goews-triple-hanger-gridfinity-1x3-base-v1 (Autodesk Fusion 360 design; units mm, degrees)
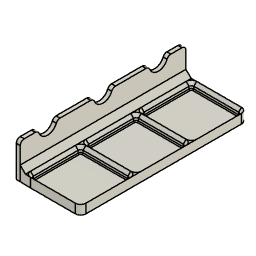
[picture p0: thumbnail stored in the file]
base_feature "Base Feature1" bodies "Triple Plate Blank"
fillet "Fillet1" radius 3
copy_paste_bodies "CutPasteBodies"
align "Align1"
align "Align2"
align "Align3"
move "Move1"
copy_paste_bodies "CopyPasteBodies2"
move "Move2"
copy_paste_bodies "CopyPasteBodies3"
move "Move3"
combine "Combine1" bodies "Grid (1)", "Grid (1) (1)"
sketch "Sketch1" plane through (0, 0, -142.1244) normal (0, 0, -1) x axis (1, 0, 0)
  line L1 (99.15, -104.8) -> (96.15, -104.8)
  line L2 (99.15, 20.8) -> (99.15, -104.8)
  line L3 (96.15, 20.8) -> (99.15, 20.8)
  line L4 (96.15, 15.3) -> (96.15, 20.8)
  line L5 (96.15, -15.3) -> (96.15, 15.3)
  line L6 (96.15, -26.7) -> (96.15, -15.3)
  line L7 (96.15, -57.3) -> (96.15, -26.7)
  line L8 (96.15, -68.7) -> (96.15, -57.3)
  line L9 (96.15, -99.3) -> (96.15, -68.7)
  line L10 (96.15, -104.8) -> (96.15, -99.3)
  line L11 (141.15, -65.8464) -> (107.15, -65.8464)
  line L12 (142.3036, -101) -> (142.3036, -67)
  line L13 (107.15, -102.1536) -> (141.15, -102.1536)
  line L14 (105.9964, -67) -> (105.9964, -101)
  line L15 (141.15, -23.8464) -> (107.15, -23.8464)
  line L16 (142.3036, -59) -> (142.3036, -25)
  line L17 (107.15, -60.1536) -> (141.15, -60.1536)
  line L18 (105.9964, -25) -> (105.9964, -59)
  line L19 (107.15, 21) -> (141.15, 21)
  line L20 (103.15, -17) -> (103.15, 17)
  line L21 (103.15, -59) -> (103.15, -25)
  line L22 (103.15, -101) -> (103.15, -67)
  line L23 (141.15, -105) -> (107.15, -105)
  line L24 (145.15, -67) -> (145.15, -101)
  line L25 (145.15, -25) -> (145.15, -59)
  line L26 (145.15, 17) -> (145.15, -17)
  line L27 (141.15, 18.1536) -> (107.15, 18.1536)
  line L28 (142.3036, -17) -> (142.3036, 17)
  line L29 (107.15, -18.1536) -> (141.15, -18.1536)
  line L30 (105.9964, 17) -> (105.9964, -17)
  line L31 (107.0494, 20.9987) -> (99.15, 20.8)
  line L32 (107.0494, -104.9987) -> (99.15, -104.8)
  arc A1 centre (107.15, -67) radius 1.1536 clockwise from (105.9964, -67) to (107.15, -65.8464)
  arc A2 centre (141.15, -67) radius 1.1536 clockwise from (141.15, -65.8464) to (142.3036, -67)
  arc A3 centre (141.15, -101) radius 1.1536 clockwise from (142.3036, -101) to (141.15, -102.1536)
  arc A4 centre (107.15, -101) radius 1.1536 clockwise from (107.15, -102.1536) to (105.9964, -101)
  arc A5 centre (107.15, -25) radius 1.1536 clockwise from (105.9964, -25) to (107.15, -23.8464)
  arc A6 centre (141.15, -25) radius 1.1536 clockwise from (141.15, -23.8464) to (142.3036, -25)
  arc A7 centre (141.15, -59) radius 1.1536 clockwise from (142.3036, -59) to (141.15, -60.1536)
  arc A8 centre (107.15, -59) radius 1.1536 clockwise from (107.15, -60.1536) to (105.9964, -59)
  arc A9 centre (141.15, 17) radius 4 clockwise from (141.15, 21) to (145.15, 17)
  arc A10 centre (107.15, 17) radius 4 clockwise from (103.15, 17) to (107.15, 21)
  arc A11 centre (107.15, -17) radius 4 clockwise from (107.15, -21) to (103.15, -17)
  arc A12 centre (107.15, -25) radius 4 clockwise from (103.15, -25) to (107.15, -21)
  arc A13 centre (107.15, -59) radius 4 clockwise from (107.15, -63) to (103.15, -59)
  arc A14 centre (107.15, -67) radius 4 clockwise from (103.15, -67) to (107.15, -63)
  arc A15 centre (107.15, -101) radius 4 clockwise from (107.15, -105) to (103.15, -101)
  arc A16 centre (141.15, -101) radius 4 clockwise from (145.15, -101) to (141.15, -105)
  arc A17 centre (141.15, -67) radius 4 clockwise from (141.15, -63) to (145.15, -67)
  arc A18 centre (141.15, -59) radius 4 clockwise from (145.15, -59) to (141.15, -63)
  arc A19 centre (141.15, -25) radius 4 clockwise from (141.15, -21) to (145.15, -25)
  arc A20 centre (141.15, -17) radius 4 clockwise from (145.15, -17) to (141.15, -21)
  arc A21 centre (107.15, 17) radius 1.1536 clockwise from (105.9964, 17) to (107.15, 18.1536)
  arc A22 centre (141.15, 17) radius 1.1536 clockwise from (141.15, 18.1536) to (142.3036, 17)
  arc A23 centre (141.15, -17) radius 1.1536 clockwise from (142.3036, -17) to (141.15, -18.1536)
  arc A24 centre (107.15, -17) radius 1.1536 clockwise from (107.15, -18.1536) to (105.9964, -17)
  point P4 (99.15, 20.8)
  point P68 (99.15, 20.8)
  point P69 (107.0494, 20.9987)
  point P3 (99.15, -104.8)
  point P70 (99.15, -104.8)
  point P71 (107.0494, -104.9987)
  coincident P4 P68
  coincident A10 P69
  tangent A10 L31
  coincident P3 P70
  coincident A15 P71
  tangent A15 L32
extrude "Extrude1" add sketch "Sketch1" profile of L2 A10 L20 A11 A12 L21 A13 A14 L22 A15 L31 L32 against normal blind 4.646 bodies "Grid"
chamfer "Chamfer1" distance 4
sketch "Sketch2" plane through (0, 0, -142.1244) normal (0, 0, -1) x axis (1, 0, 0)
  line L1 (141.15, 18.1536) -> (107.15, 18.1536)
  line L2 (142.3036, -17) -> (142.3036, 17)
  line L3 (107.15, -18.1536) -> (141.15, -18.1536)
  line L4 (105.9964, 17) -> (105.9964, -17)
  line L5 (141.15, -23.8464) -> (107.15, -23.8464)
  line L6 (142.3036, -59) -> (142.3036, -25)
  line L7 (107.15, -60.1536) -> (141.15, -60.1536)
  line L8 (105.9964, -25) -> (105.9964, -59)
  line L9 (141.15, -65.8464) -> (107.15, -65.8464)
  line L10 (142.3036, -101) -> (142.3036, -67)
  line L11 (107.15, -102.1536) -> (141.15, -102.1536)
  line L12 (105.9964, -67) -> (105.9964, -101)
  line L13 (99.15, -104.8) -> (96.15, -104.8)
  line L14 (107.0494, -104.9987) -> (99.15, -104.8)
  line L15 (141.15, -105) -> (107.15, -105)
  line L16 (145.15, -67) -> (145.15, -101)
  line L17 (145.15, -25) -> (145.15, -59)
  line L18 (145.15, 17) -> (145.15, -17)
  line L19 (107.15, 21) -> (141.15, 21)
  line L20 (99.15, 20.8) -> (107.0494, 20.9987)
  line L21 (96.15, 20.8) -> (99.15, 20.8)
  line L22 (96.15, 15.3) -> (96.15, 20.8)
  line L23 (96.15, -15.3) -> (96.15, 15.3)
  line L24 (96.15, -26.7) -> (96.15, -15.3)
  line L25 (96.15, -57.3) -> (96.15, -26.7)
  line L26 (96.15, -68.7) -> (96.15, -57.3)
  line L27 (96.15, -99.3) -> (96.15, -68.7)
  line L28 (96.15, -104.8) -> (96.15, -99.3)
  line L29 (145.15, -25) -> (145.15, -17)
  line L30 (145.15, -67) -> (145.15, -59)
  arc A1 centre (107.15, 17) radius 1.1536 clockwise from (105.9964, 17) to (107.15, 18.1536)
  arc A2 centre (141.15, 17) radius 1.1536 clockwise from (141.15, 18.1536) to (142.3036, 17)
  arc A3 centre (141.15, -17) radius 1.1536 clockwise from (142.3036, -17) to (141.15, -18.1536)
  arc A4 centre (107.15, -17) radius 1.1536 clockwise from (107.15, -18.1536) to (105.9964, -17)
  arc A5 centre (107.15, -25) radius 1.1536 clockwise from (105.9964, -25) to (107.15, -23.8464)
  arc A6 centre (141.15, -25) radius 1.1536 clockwise from (141.15, -23.8464) to (142.3036, -25)
  arc A7 centre (141.15, -59) radius 1.1536 clockwise from (142.3036, -59) to (141.15, -60.1536)
  arc A8 centre (107.15, -59) radius 1.1536 clockwise from (107.15, -60.1536) to (105.9964, -59)
  arc A9 centre (107.15, -67) radius 1.1536 clockwise from (105.9964, -67) to (107.15, -65.8464)
  arc A10 centre (141.15, -67) radius 1.1536 clockwise from (141.15, -65.8464) to (142.3036, -67)
  arc A11 centre (141.15, -101) radius 1.1536 clockwise from (142.3036, -101) to (141.15, -102.1536)
  arc A12 centre (107.15, -101) radius 1.1536 clockwise from (107.15, -102.1536) to (105.9964, -101)
  arc A13 centre (107.15, -101) radius 4 clockwise from (107.15, -105) to (107.0494, -104.9987)
  arc A14 centre (141.15, -101) radius 4 clockwise from (145.15, -101) to (141.15, -105)
  arc A15 centre (141.15, -67) radius 4 clockwise from (141.15, -63) to (145.15, -67)
  arc A16 centre (141.15, -59) radius 4 clockwise from (145.15, -59) to (141.15, -63)
  arc A17 centre (141.15, -25) radius 4 clockwise from (141.15, -21) to (145.15, -25)
  arc A18 centre (141.15, -17) radius 4 clockwise from (145.15, -17) to (141.15, -21)
  arc A19 centre (141.15, 17) radius 4 clockwise from (141.15, 21) to (145.15, 17)
  arc A20 centre (107.15, 17) radius 4 clockwise from (107.0494, 20.9987) to (107.15, 21)
  point P49 (145.15, -17)
  point P62 (145.15, -17)
  point P47 (145.15, -25)
  point P63 (145.15, -25)
  point P46 (145.15, -59)
  point P64 (145.15, -59)
  point P44 (145.15, -67)
  point P65 (145.15, -67)
  coincident P49 P62
  coincident P47 P63
  coincident P46 P64
  coincident P44 P65
extrude "Extrude2" add sketch "Sketch2" profile of A6 A15 A16 A17 A18 L29 L30 against normal blind 4.646
move_face "MoveFace1"
move_face "MoveFace2"
sketch "Sketch3" plane through (0, 0, -142.1244) normal (0, 0, -1) x axis (1, 0, 0)
  line L1 (141.15, 18.1536) -> (107.15, 18.1536)
  line L2 (142.3036, -17) -> (142.3036, 17)
  line L3 (107.15, -18.1536) -> (141.15, -18.1536)
  line L4 (105.9964, 17) -> (105.9964, -17)
  line L5 (141.15, -23.8464) -> (107.15, -23.8464)
  line L6 (142.3036, -59) -> (142.3036, -25)
  line L7 (107.15, -60.1536) -> (141.15, -60.1536)
  line L8 (105.9964, -25) -> (105.9964, -59)
  line L9 (141.15, -65.8464) -> (107.15, -65.8464)
  line L10 (142.3036, -101) -> (142.3036, -67)
  line L11 (107.15, -102.1536) -> (141.15, -102.1536)
  line L12 (105.9964, -67) -> (105.9964, -101)
  line L13 (99.15, -104.8) -> (96.15, -104.8)
  line L14 (107.0494, -104.9987) -> (99.15, -104.8)
  line L15 (141.15, -105) -> (107.15, -105)
  line L16 (145.15, 17) -> (145.15, -101)
  line L17 (107.15, 21) -> (141.15, 21)
  line L18 (99.15, 20.8) -> (107.0494, 20.9987)
  line L19 (96.15, 20.8) -> (99.15, 20.8)
  line L20 (96.15, 15.1) -> (96.15, 20.8)
  line L21 (96.15, -15.1) -> (96.15, 15.1)
  line L22 (96.15, -26.9) -> (96.15, -15.1)
  line L23 (96.15, -57.1) -> (96.15, -26.9)
  line L24 (96.15, -68.9) -> (96.15, -57.1)
  line L25 (96.15, -99.1) -> (96.15, -68.9)
  line L26 (96.15, -104.8) -> (96.15, -99.1)
  arc A1 centre (107.15, 17) radius 1.1536 clockwise from (105.9964, 17) to (107.15, 18.1536)
  arc A2 centre (141.15, 17) radius 1.1536 clockwise from (141.15, 18.1536) to (142.3036, 17)
  arc A3 centre (141.15, -17) radius 1.1536 clockwise from (142.3036, -17) to (141.15, -18.1536)
  arc A4 centre (107.15, -17) radius 1.1536 clockwise from (107.15, -18.1536) to (105.9964, -17)
  arc A5 centre (107.15, -25) radius 1.1536 clockwise from (105.9964, -25) to (107.15, -23.8464)
  arc A6 centre (141.15, -25) radius 1.1536 clockwise from (141.15, -23.8464) to (142.3036, -25)
  arc A7 centre (141.15, -59) radius 1.1536 clockwise from (142.3036, -59) to (141.15, -60.1536)
  arc A8 centre (107.15, -59) radius 1.1536 clockwise from (107.15, -60.1536) to (105.9964, -59)
  arc A9 centre (107.15, -67) radius 1.1536 clockwise from (105.9964, -67) to (107.15, -65.8464)
  arc A10 centre (141.15, -67) radius 1.1536 clockwise from (141.15, -65.8464) to (142.3036, -67)
  arc A11 centre (141.15, -101) radius 1.1536 clockwise from (142.3036, -101) to (141.15, -102.1536)
  arc A12 centre (107.15, -101) radius 1.1536 clockwise from (107.15, -102.1536) to (105.9964, -101)
  arc A13 centre (107.15, -101) radius 4 clockwise from (107.15, -105) to (107.0494, -104.9987)
  arc A14 centre (141.15, -101) radius 4 clockwise from (145.15, -101) to (141.15, -105)
  arc A15 centre (141.15, 17) radius 4 clockwise from (141.15, 21) to (145.15, 17)
  arc A16 centre (107.15, 17) radius 4 clockwise from (107.0494, 20.9987) to (107.15, 21)
extrude "Extrude3" add sketch "Sketch3" along normal blind 2.354
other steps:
base_feature "Base Feature2" bodies "Grid"
base_feature "Base Feature3" bodies "Grid", "Grid (1)"
base_feature "Base Feature4" bodies "Grid (1)", "Grid (1) (1)"
named bodies: "Triple Plate Blank", "Grid", "Grid (1)", "Grid (1) (1)"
